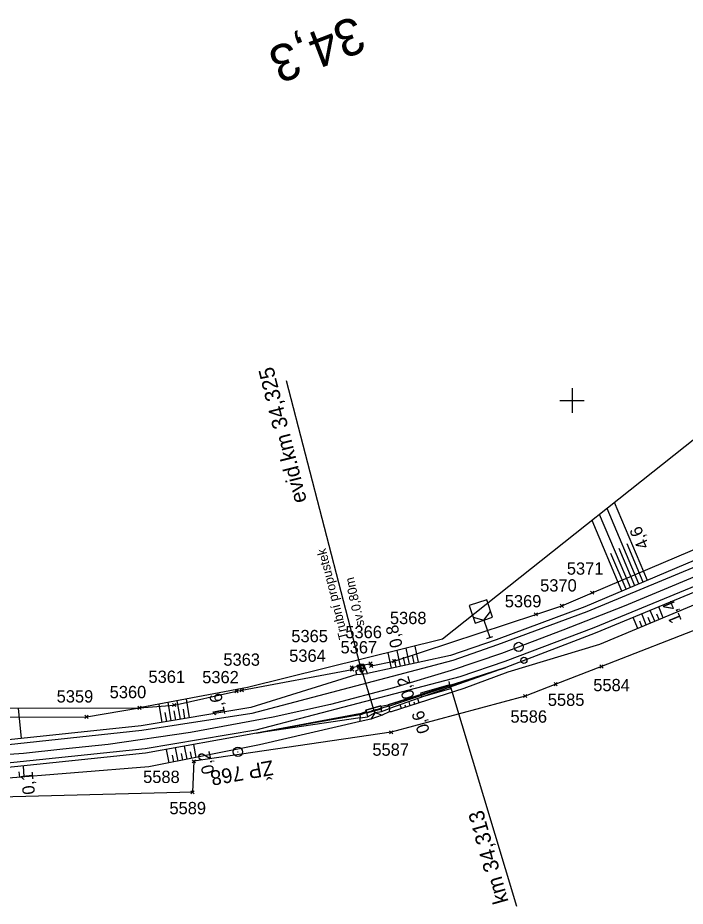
# Model space of a CAD drawing. Extents: x -805730 to -804640, y -1150889 to -1150366.
# Drawn here: x -805190.1 to -805081.6, y -1150682.3 to -1150537.8 of the extents above; entities that cross this region are included whole.
import ezdxf

# ---------------------------------------------------------------- set-up
doc = ezdxf.new("R2010")
doc.units = 0
for name, color, linetype in [('0381KM032-037P - Vrstva 1', 7, 'Continuous'), ('0381KM032-037P - Vrstva 13', 7, 'Continuous'), ('0381KM032-037P - Vrstva 17', 7, 'Continuous'), ('0381KM032-037P - Vrstva 19', 7, 'Continuous'), ('0381KM032-037P - Vrstva 4', 7, 'Continuous'), ('0381KM032-037P - Vrstva 48', 7, 'Continuous'), ('0381KM032-037P - Vrstva 49', 7, 'Continuous'), ('0381KM032-037P - Vrstva 7', 7, 'Continuous'), ('0381KM032-037P - Vrstva 9', 7, 'Continuous'), ('krizky_1000 - Vrstva 1', 7, 'Continuous'), ('szdc - hran DP', 7, 'Continuous'), ('szdc - szdc_cislo', 7, 'Continuous'), ('szdc - szdc_krizek', 7, 'Continuous'), ('vyt_sit - stávající', 7, 'Continuous')]:
    doc.layers.add(name, color=color, linetype=linetype)

msp = doc.modelspace()

# ---------------------------------------------------------------- linework, layer by layer
at = {"layer": '0381KM032-037P - Vrstva 1'}
for points in [[(-805074.24, -1150626.27), (-805091.51, -1150633.48)], [(-805091.51, -1150633.48), (-805101.49, -1150637.38), (-805111.46, -1150641.17)], [(-805111.46, -1150641.17), (-805119.63, -1150643.91), (-805129.05, -1150646.75), (-805139.28, -1150649.43), (-805148.59, -1150651.52), (-805162.04, -1150654.03), (-805175.42, -1150655.94), (-805182.79, -1150656.72)], [(-805182.79, -1150656.72), (-805189.2, -1150657.4), (-805199.42, -1150658.12), (-805222.35, -1150659), (-805235.71, -1150659.34), (-805248.65, -1150659.92), (-805262.34, -1150660.99)]]:
    msp.add_lwpolyline(points, dxfattribs=at)
at = {"layer": '0381KM032-037P - Vrstva 13'}
for p, q in [((-805129.78, -1150649.7), (-805129.65, -1150650.12)), ((-805133.42, -1150650.74), (-805132.59, -1150650.52)), ((-805133.42, -1150650.74), (-805133.23, -1150651.44)), ((-805131.99, -1150650.77), (-805132.69, -1150651.85)), ((-805131.99, -1150650.77), (-805132.2, -1150650.41)), ((-805131.99, -1150650.77), (-805130.88, -1150651.21)), ((-805131, -1150650.07), (-805131.81, -1150650.3)), ((-805130.99, -1150650.58), (-805131, -1150650.07))]:
    msp.add_line(p, q, dxfattribs=at)
for points in [[(-805129.89, -1150649.51), (-805129.78, -1150649.7), (-805131, -1150650.07), (-805131, -1150650.07), (-805131.07, -1150649.74), (-805129.89, -1150649.51)], [(-805134.49, -1150651.14), (-805134.56, -1150650.98), (-805133.46, -1150650.58), (-805133.42, -1150650.74), (-805133.42, -1150650.74), (-805134.49, -1150651.14), (-805134.45, -1150651.61)], [(-805129.65, -1150650.12), (-805129.71, -1150650.67), (-805130.88, -1150651.21), (-805132.69, -1150651.85), (-805134.43, -1150652.2), (-805134.45, -1150651.61), (-805133.23, -1150651.44)], [(-805133.23, -1150651.44), (-805131.99, -1150650.77), (-805130.99, -1150650.58)], [(-805130.99, -1150650.58), (-805129.65, -1150650.12)]]:
    msp.add_lwpolyline(points, dxfattribs=at)
msp.add_ellipse((-805132.2, -1150650.41), major_axis=(-0.388, -0.106), ratio=0.004829, start_param=3.14712, end_param=6.275171, dxfattribs=at)
at = {"layer": '0381KM032-037P - Vrstva 17'}
msp.add_lwpolyline([(-805070.8, -1150598.9), (-805121.06, -1150638.84), (-805152.76, -1150646.7), (-805170.92, -1150650.08), (-805194.39, -1150650.05), (-805213.2, -1150651.26), (-805221.79, -1150652.33), (-805228.79, -1150654.03)], dxfattribs=at)
at = {"layer": '0381KM032-037P - Vrstva 19'}
for p, q in [((-805146.46, -1150596.75), (-805134.12, -1150644.47)), ((-805133.42, -1150650.74), (-805132.59, -1150650.52)), ((-805133.42, -1150650.74), (-805133.42, -1150650.74)), ((-805133.38, -1150650.83), (-805130.98, -1150650.17)), ((-805133.38, -1150650.83), (-805130.98, -1150650.17)), ((-805131.81, -1150650.3), (-805131, -1150650.07))]:
    msp.add_line(p, q, dxfattribs=at)
for points in [[(-805134.98, -1150644.55), (-805135.16, -1150643.96), (-805134.72, -1150643.76), (-805134.94, -1150643.05), (-805134.71, -1150643.05), (-805134.48, -1150643.83)], [(-805134.98, -1150644.55), (-805133.26, -1150644.39), (-805133.87, -1150642.97), (-805134.1, -1150642.94), (-805133.82, -1150643.72)], [(-805134.1, -1150642.94), (-805134.37, -1150642.96), (-805134.71, -1150643.05)], [(-805134.37, -1150642.96), (-805134.35, -1150643.15), (-805134.27, -1150643.62), (-805132.2, -1150650.41)], [(-805133.52, -1150650.35), (-805133.38, -1150650.83), (-805133.38, -1150650.83), (-805133.42, -1150650.74), (-805131, -1150650.07), (-805130.98, -1150650.17), (-805130.98, -1150650.17), (-805131.11, -1150649.68), (-805133.52, -1150650.35)], [(-805131.11, -1150649.68), (-805131.11, -1150649.68), (-805131.07, -1150649.74), (-805131, -1150650.07), (-805131, -1150650.07)], [(-805133.52, -1150650.35), (-805133.52, -1150650.35), (-805133.46, -1150650.58), (-805133.42, -1150650.74)]]:
    msp.add_lwpolyline(points, dxfattribs=at)
for centre, major_axis, ratio, start_param, end_param in [((-805134.15, -1150643.86), (0.331, 0.133), 0.755735, 2.535553, 6.304808), ((-805134.15, -1150643.86), (0.331, 0.133), 0.755735, 0.021623, 2.535553), ((-805132.2, -1150650.41), (0.388, 0.106), 0.004829, 1.569477, 6.288713), ((-805132.2, -1150650.41), (-0.388, -0.106), 0.004829, 3.14712, 4.71107)]:
    msp.add_ellipse(centre, major_axis=major_axis, ratio=ratio, start_param=start_param, end_param=end_param, dxfattribs=at)
at = {"layer": '0381KM032-037P - Vrstva 4'}
for points in [[(-804872.17, -1150539.66), (-804893.72, -1150547.52), (-804911.96, -1150555), (-804952.93, -1150572.63), (-804995.29, -1150590.69), (-805039.86, -1150609.18), (-805057.83, -1150616.69), (-805068.36, -1150621.07), (-805097.92, -1150633.57)], [(-804864.42, -1150538.53), (-804893.06, -1150548.77), (-804911.6, -1150556.2), (-804952.82, -1150573.68), (-804994.86, -1150591.44), (-805039.39, -1150610.13), (-805056.71, -1150617.44), (-805097.6, -1150634.39)], [(-804862.73, -1150542.41), (-804863.39, -1150541.46), (-804892.29, -1150551.48), (-804910.22, -1150558.86), (-804951.61, -1150576.23), (-804993.7, -1150593.96), (-805038.63, -1150612.92), (-805049.62, -1150617.53), (-805055.59, -1150619.94), (-805066.74, -1150624.75), (-805096.44, -1150637.01)], [(-804864.94, -1150543.15), (-804869.59, -1150544.8), (-804891.93, -1150552.26), (-804909.8, -1150559.87), (-804951.24, -1150577.2), (-804993.38, -1150594.6), (-805038.39, -1150613.8), (-805059.54, -1150622.79), (-805066.49, -1150625.57), (-805096.25, -1150637.87)], [(-805097.92, -1150633.57), (-805112.32, -1150638.96), (-805119.74, -1150641.46), (-805133.26, -1150644.39)], [(-805097.6, -1150634.39), (-805112.1, -1150639.75), (-805119.36, -1150642.27), (-805152.08, -1150650.89), (-805169.94, -1150653.7), (-805193.71, -1150656.24), (-805212.28, -1150657.22)], [(-805096.44, -1150637.01), (-805110.9, -1150642.46), (-805118.26, -1150644.98), (-805151.42, -1150653.61), (-805169.41, -1150656.67), (-805193.4, -1150659.17), (-805212.01, -1150660.08)], [(-805096.25, -1150637.87), (-805110.77, -1150643.45), (-805117.97, -1150645.76), (-805129.89, -1150649.51)], [(-805134.98, -1150644.55), (-805152.23, -1150649.93), (-805170.06, -1150652.94), (-805193.76, -1150655.4), (-805212.2, -1150656.84), (-805228.99, -1150656.61)], [(-805134.56, -1150650.98), (-805151.31, -1150654.12), (-805169.36, -1150657.36), (-805193.31, -1150659.84), (-805211.96, -1150660.88), (-805220.23, -1150661.07)]]:
    msp.add_lwpolyline(points, dxfattribs=at)
at = {"layer": '0381KM032-037P - Vrstva 48'}
for p, q in [((-805089.11, -1150629.85), (-805094.3, -1150617.57)), ((-805087.73, -1150629.26), (-805093.08, -1150616.6)), ((-805090.49, -1150630.43), (-805095.52, -1150618.54)), ((-805091.87, -1150631.02), (-805096.74, -1150619.51)), ((-805088.42, -1150629.55), (-805091.05, -1150623.32)), ((-805091.18, -1150630.72), (-805093.66, -1150624.87)), ((-805089.8, -1150630.14), (-805092.35, -1150624.1)), ((-805085.16, -1150635.34), (-805085.89, -1150633.59)), ((-805087.93, -1150636.49), (-805088.67, -1150634.73)), ((-805086.55, -1150635.91), (-805087.28, -1150634.16)), ((-805085.85, -1150635.62), (-805086.22, -1150634.75)), ((-805089.32, -1150637.07), (-805090.05, -1150635.3)), ((-805088.62, -1150636.78), (-805088.99, -1150635.9)), ((-805087.24, -1150636.2), (-805087.61, -1150635.32)), ((-805129.34, -1150643.54), (-805129.89, -1150641.03)), ((-805127.87, -1150643.22), (-805128.43, -1150640.67)), ((-805126.41, -1150642.91), (-805126.97, -1150640.3)), ((-805124.94, -1150642.59), (-805125.52, -1150639.94)), ((-805128.61, -1150643.38), (-805128.88, -1150642.11)), ((-805127.14, -1150643.06), (-805127.42, -1150641.78)), ((-805125.68, -1150642.75), (-805125.96, -1150641.44)), ((-805125.89, -1150648.25), (-805125.84, -1150648.39)), ((-805166.64, -1150652.36), (-805167.14, -1150649.38)), ((-805165.16, -1150652.11), (-805165.66, -1150649.1)), ((-805163.68, -1150651.86), (-805164.19, -1150648.83)), ((-805162.2, -1150651.61), (-805162.71, -1150648.55)), ((-805128.75, -1150649.15), (-805128.69, -1150649.34)), ((-805128.03, -1150648.93), (-805128.01, -1150649.01)), ((-805127.72, -1150650.11), (-805127.92, -1150649.5)), ((-805127.32, -1150648.7), (-805127.27, -1150648.86)), ((-805127.01, -1150649.88), (-805127.11, -1150649.57)), ((-805126.6, -1150648.48), (-805126.58, -1150648.55)), ((-805126.29, -1150649.66), (-805126.5, -1150649)), ((-805125.58, -1150649.43), (-805125.69, -1150649.09)), ((-805124.86, -1150649.2), (-805125.09, -1150648.51)), ((-805189.5, -1150654.96), (-805190.01, -1150650.05)), ((-805165.9, -1150652.24), (-805166.15, -1150650.74)), ((-805164.42, -1150651.99), (-805164.67, -1150650.48)), ((-805162.94, -1150651.74), (-805163.19, -1150650.22)), ((-805165.5, -1150658.95), (-805165.94, -1150656.75)), ((-805164.03, -1150658.66), (-805164.46, -1150656.48)), ((-805162.56, -1150658.36), (-805162.99, -1150656.22)), ((-805161.09, -1150658.07), (-805161.51, -1150655.95)), ((-805164.77, -1150658.8), (-805164.98, -1150657.71)), ((-805163.3, -1150658.51), (-805163.51, -1150657.43)), ((-805161.82, -1150658.22), (-805162.04, -1150657.15)), ((-805189.06, -1150661.23), (-805189.2, -1150659.41)), ((-805189.8, -1150661.29), (-805189.88, -1150660.39))]:
    msp.add_line(p, q, dxfattribs=at)
at = {"layer": '0381KM032-037P - Vrstva 49'}
for p, q in [((-805134.98, -1150644.55), (-805133.26, -1150644.39)), ((-805129.78, -1150649.7), (-805117.97, -1150645.76)), ((-805134.49, -1150651.14), (-805151.31, -1150654.12)), ((-805134.45, -1150651.61), (-805151.31, -1150654.12))]:
    msp.add_line(p, q, dxfattribs=at)
for points in [[(-804871.36, -1150538.86), (-804872.17, -1150539.66), (-804893.72, -1150547.52), (-804911.96, -1150555), (-804952.93, -1150572.63), (-804995.29, -1150590.69), (-805039.86, -1150609.18), (-805057.83, -1150616.69), (-805068.36, -1150621.07), (-805097.92, -1150633.57)], [(-804909.8, -1150559.87), (-804951.24, -1150577.2), (-804993.38, -1150594.6), (-805038.39, -1150613.8), (-805050.01, -1150619.25), (-805055.21, -1150621.51), (-805059.54, -1150622.79), (-805066.49, -1150625.57), (-805096.25, -1150637.87)], [(-805070.8, -1150598.9), (-805121.06, -1150638.84), (-805152.76, -1150646.7), (-805170.92, -1150650.08), (-805194.39, -1150650.05), (-805213.2, -1150651.26), (-805221.79, -1150652.33), (-805228.79, -1150654.03)], [(-805065.73, -1150627.22), (-805095.53, -1150639.67)], [(-805097.92, -1150633.57), (-805112.32, -1150638.96), (-805119.74, -1150641.46), (-805133.26, -1150644.39)], [(-805096.25, -1150637.87), (-805110.77, -1150643.45), (-805129.65, -1150650.12)], [(-805095.53, -1150639.67), (-805110.42, -1150644.21), (-805117.6, -1150646.87), (-805129.42, -1150650.66)], [(-805129.89, -1150649.51), (-805117.97, -1150645.76), (-805110.77, -1150643.45)], [(-805134.98, -1150644.55), (-805152.23, -1150649.93), (-805170.06, -1150652.94), (-805193.76, -1150655.4), (-805212.2, -1150656.84), (-805221.82, -1150655.55)], [(-805151.31, -1150654.12), (-805134.56, -1150650.98), (-805133.46, -1150650.58), (-805133.52, -1150650.35), (-805133.52, -1150650.35), (-805131.11, -1150649.68), (-805131.11, -1150649.68), (-805131.07, -1150649.74), (-805129.89, -1150649.51)], [(-805129.78, -1150649.7), (-805131, -1150650.07), (-805131.81, -1150650.3)], [(-805134.49, -1150651.14), (-805133.42, -1150650.74), (-805132.59, -1150650.52)], [(-805134.45, -1150651.61), (-805133.23, -1150651.44), (-805131.99, -1150650.77), (-805130.99, -1150650.58), (-805129.65, -1150650.12)], [(-805129.42, -1150650.66), (-805129.71, -1150650.67), (-805130.88, -1150651.21), (-805132.69, -1150651.85), (-805134.43, -1150652.2)], [(-805134.43, -1150652.2), (-805150.83, -1150656.03), (-805168.82, -1150659.61), (-805193.05, -1150661.55), (-805211.83, -1150662.42), (-805220.04, -1150663.05)], [(-805151.31, -1150654.12), (-805169.36, -1150657.36), (-805193.31, -1150659.84), (-805211.96, -1150660.88), (-805220.13, -1150661.62)]]:
    msp.add_lwpolyline(points, dxfattribs=at)
msp.add_ellipse((-805132.2, -1150650.41), major_axis=(0.388, 0.106), ratio=0.004829, start_param=0.005528, end_param=3.133579, dxfattribs=at)
at = {"layer": '0381KM032-037P - Vrstva 7'}
for p, q in [((-805114.33, -1150635.74), (-805113.38, -1150638.58)), ((-805113.85, -1150638.74), (-805112.9, -1150638.42)), ((-805107.87, -1150642.28), (-805107.77, -1150642.28))]:
    msp.add_line(p, q, dxfattribs=at)
for points in [[(-805114.33, -1150635.74), (-805112.91, -1150635.26), (-805113.86, -1150632.42), (-805116.71, -1150633.37), (-805115.75, -1150636.22), (-805114.33, -1150635.74)], [(-805116.07, -1150635.27), (-805114.33, -1150635.74), (-805113.23, -1150634.31)]]:
    msp.add_lwpolyline(points, dxfattribs=at)
for centre, radius in [((-805108.67, -1150640.09), 0.75), ((-805107.82, -1150642.28), 0.5)]:
    msp.add_circle(centre, radius, dxfattribs=at)
at = {"layer": '0381KM032-037P - Vrstva 9'}
for p, q in [((-805119.84, -1150646.28), (-805124.65, -1150647.63)), ((-805119.84, -1150646.28), (-805120, -1150645.7)), ((-805119.68, -1150646.86), (-805119.84, -1150646.28)), ((-805119.76, -1150646.57), (-805109, -1150682.26)), ((-805124.65, -1150647.63), (-805124.49, -1150648.21)), ((-805124.49, -1150648.21), (-805119.68, -1150646.86))]:
    msp.add_line(p, q, dxfattribs=at)
at = {"layer": 'krizky_1000 - Vrstva 1'}
for points in [[(-805100, -1150598), (-805100, -1150602)], [(-805102, -1150600), (-805098, -1150600)]]:
    msp.add_lwpolyline(points, dxfattribs=at)
at = {"layer": 'szdc - hran DP'}
for p, q in [((-805096.7, -1150631.27), (-805066.7, -1150618.51)), ((-805101.66, -1150633.38), (-805096.7, -1150631.27)), ((-805105.89, -1150634.79), (-805101.66, -1150633.38)), ((-805128.92, -1150642.38), (-805105.89, -1150634.79)), ((-805077.33, -1150636.32), (-805095.21, -1150643.26)), ((-805132.67, -1150643.17), (-805128.92, -1150642.38)), ((-805153.67, -1150647.14), (-805135.75, -1150643.74)), ((-805135.82, -1150643.41), (-805132.75, -1150642.8)), ((-805135.75, -1150643.74), (-805135.82, -1150643.41)), ((-805132.75, -1150642.8), (-805132.67, -1150643.17)), ((-805095.21, -1150643.26), (-805102.65, -1150646.15)), ((-805102.65, -1150646.15), (-805107.63, -1150648.08)), ((-805164.69, -1150649.54), (-805154.57, -1150647.29)), ((-805154.57, -1150647.29), (-805153.67, -1150647.14)), ((-805107.63, -1150648.08), (-805129.38, -1150653.98)), ((-805170.32, -1150649.99), (-805164.69, -1150649.54)), ((-805178.93, -1150651.45), (-805170.32, -1150649.99)), ((-805208.17, -1150651.53), (-805178.93, -1150651.45)), ((-805129.38, -1150653.98), (-805161.49, -1150658.69)), ((-805161.49, -1150658.69), (-805161.69, -1150663.73)), ((-805161.69, -1150663.73), (-805193.03, -1150664.54))]:
    msp.add_line(p, q, dxfattribs=at)
at = {"layer": 'szdc - szdc_krizek'}
for p, q in [((-805096.44, -1150631.53), (-805096.97, -1150631.01)), ((-805096.97, -1150631.53), (-805096.44, -1150631.01)), ((-805101.4, -1150633.65), (-805101.93, -1150633.11)), ((-805101.93, -1150633.65), (-805101.4, -1150633.11)), ((-805105.62, -1150635.05), (-805106.16, -1150634.53)), ((-805106.16, -1150635.05), (-805105.62, -1150634.53)), ((-805128.66, -1150642.65), (-805129.19, -1150642.11)), ((-805129.19, -1150642.65), (-805128.66, -1150642.11)), ((-805135.56, -1150643.68), (-805136.09, -1150643.15)), ((-805136.09, -1150643.68), (-805135.56, -1150643.15)), ((-805135.48, -1150644.01), (-805136.02, -1150643.48)), ((-805136.02, -1150644.01), (-805135.48, -1150643.48)), ((-805132.48, -1150643.06), (-805133.02, -1150642.53)), ((-805133.02, -1150643.06), (-805132.48, -1150642.53)), ((-805132.41, -1150643.44), (-805132.94, -1150642.91)), ((-805132.94, -1150643.44), (-805132.41, -1150642.91)), ((-805094.95, -1150643.53), (-805095.48, -1150643)), ((-805095.48, -1150643.53), (-805094.95, -1150643)), ((-805102.39, -1150646.42), (-805102.92, -1150645.89)), ((-805102.92, -1150646.42), (-805102.39, -1150645.89)), ((-805154.31, -1150647.55), (-805154.84, -1150647.03)), ((-805154.84, -1150647.55), (-805154.31, -1150647.03)), ((-805153.41, -1150647.41), (-805153.94, -1150646.88)), ((-805153.94, -1150647.41), (-805153.41, -1150646.88)), ((-805107.36, -1150648.34), (-805107.9, -1150647.81)), ((-805107.9, -1150648.34), (-805107.36, -1150647.81)), ((-805164.43, -1150649.8), (-805164.96, -1150649.28)), ((-805164.96, -1150649.8), (-805164.43, -1150649.28)), ((-805170.06, -1150650.26), (-805170.59, -1150649.73)), ((-805170.59, -1150650.26), (-805170.06, -1150649.73)), ((-805178.67, -1150651.72), (-805179.2, -1150651.19)), ((-805179.2, -1150651.72), (-805178.67, -1150651.19)), ((-805129.11, -1150654.25), (-805129.65, -1150653.72)), ((-805129.65, -1150654.25), (-805129.11, -1150653.72)), ((-805161.22, -1150658.96), (-805161.76, -1150658.43)), ((-805161.76, -1150658.96), (-805161.22, -1150658.43)), ((-805161.43, -1150664), (-805161.96, -1150663.47)), ((-805161.96, -1150664), (-805161.43, -1150663.47))]:
    msp.add_line(p, q, dxfattribs=at)
at = {"layer": 'vyt_sit - stávající'}
msp.add_line((-805154.38, -1150657.15), (-805154.28, -1150657.15), dxfattribs=at)
msp.add_circle((-805154.33, -1150657.15), 0.756, dxfattribs=at)

# ---------------------------------------------------------------- texts
at = {"layer": '0381KM032-037P - Vrstva 19'}
for s, height, rotation, p in [('evid.km 34,325', 2.5, 104.0597, (-805143.1, -1150616.37)), ('Trubní propustek', 1.5, 104.0315, (-805136.39, -1150638.68)), ('sv.0,80m', 1.5, 102.6099, (-805133.72, -1150636.58))]:
    msp.add_text(s, height=height, rotation=rotation, dxfattribs=at).set_placement(p)
at = {"layer": '0381KM032-037P - Vrstva 48'}
for s, rotation, p in [('4,6', 113.4709, (-805087.41, -1150623.69)), ('1,4', 112.4607, (-805082.11, -1150635.78)), ('0,8', 103.9362, (-805127.51, -1150639.96)), ('0,2', 106.8529, (-805125.55, -1150648.25)), ('1,6', 100.857, (-805156.33, -1150651.13)), ('0,6', 107.7953, (-805123.1, -1150653.81)), ('0,2', 103.235, (-805158.12, -1150660.52)), ('0,1', 95.8989, (-805187.31, -1150664))]:
    msp.add_text(s, height=2, rotation=rotation, dxfattribs=at).set_placement(p)
at = {"layer": '0381KM032-037P - Vrstva 7'}
msp.add_text('34,3', height=6, rotation=201.0798, dxfattribs=at).set_placement((-805135.2, -1150537.34))
at = {"layer": '0381KM032-037P - Vrstva 9'}
msp.add_text('km 34,313', height=2.5, rotation=105.6206, dxfattribs=at).set_placement((-805110.3, -1150681.5))
at = {"layer": 'szdc - szdc_cislo'}
for s, p in [('5371', (-805100.84, -1150628.34)), ('5370', (-805105.18, -1150631.08)), ('5369', (-805110.93, -1150633.65)), ('5368', (-805129.61, -1150636.38)), ('5366', (-805136.86, -1150638.67)), ('5365', (-805145.64, -1150639.32)), ('5367', (-805137.64, -1150641.14)), ('5364', (-805145.99, -1150642.51)), ('5363', (-805156.69, -1150643.15)), ('5361', (-805168.87, -1150645.94)), ('5362', (-805160.13, -1150646)), ('5584', (-805096.54, -1150647.29)), ('5360', (-805175.18, -1150648.43)), ('5359', (-805183.8, -1150649.13)), ('5585', (-805103.93, -1150649.68)), ('5586', (-805110.01, -1150652.41)), ('5587', (-805132.46, -1150657.79)), ('5588', (-805169.74, -1150662.22)), ('5589', (-805165.46, -1150667.3))]:
    msp.add_text(s, height=2, dxfattribs=at).set_placement(p)
at = {"layer": 'vyt_sit - stávající'}
msp.add_text('ŽP 768', height=2.4, rotation=190, dxfattribs=at).set_placement((-805148.77, -1150658.51))

doc.saveas('drawing.dxf')
